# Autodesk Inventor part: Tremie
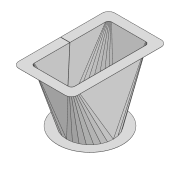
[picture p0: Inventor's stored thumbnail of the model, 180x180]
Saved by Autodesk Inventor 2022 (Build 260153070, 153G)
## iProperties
Created: 2021-07
Part Number: Tremie
Material: Générique
Document SubType Name: Sheet Metal
Designer: Fabian
Density: 1 g/cm^3
Sheet Metal Rule: Par défaut_mm
Appearance: Par défaut
Author: Fabian
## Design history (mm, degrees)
sketch "Esquisse1"
  geometry: L1 (104.999, 0.5)-(74.998, 0.5); L2 (104.999, -0.5)-(74.998, -0.5); L3 (0, 0)-(75, 0); L4 (74.998, 0.5)-(-74.998, 0.5); L5 (74.998, -0.5)-(-74.998, -0.5); A1 r 75 centre (0, 0) between (74.998, 0.5) and (74.998, -0.5); A2 r 105 centre (0, 0) between (104.999, 0.5) and (104.999, -0.5); A3 r 90 centre (0, 0) between (89.999, 0.5) and (89.999, -0.5); 2 further points
  constraints: 10 end point, 10 point on circle, 5 horizontal, 3 centre point, 2 coincident, 2 midpoint, 1 vertical alignment, 1 other
  dimensions: "d0" = 150 diameter of A1; "d1" = 1 distance between parallel lines of L2 L1; "d2" = 30 radial gap between concentric circles of A1 A2; "d3" = 15 radial gap between concentric circles of A2 A3 (= 0.5 x d2)
node "Plan de construction1"
sketch "Esquisse2"
  geometry: L1 (-55, -125)-(55, -125); L2 (55, 125)-(-55, 125); L3 (-65, 115)-(-65, -115); L4 (-65, -125)-(65, 125); L5 (65, -125)-(-65, 125); L6 (75, -155)-(-75, -155); L7 (-95, -135)-(-95, 135); L8 (-75, 155)-(75, 155); L9 (80, -140)-(80, 140); L10 (80, 140)-(-80, 140); L11 (-80, 140)-(-80, -140); L12 (-80, -140)-(80, -140); L13 (74.998, 0.5)-(-74.998, 0.5) reference; L14 (74.998, -0.5)-(-74.998, -0.5) reference; L15 (65, -115)-(65, -0.5); L16 (65, 0.5)-(65, 115); L17 (95, 135)-(95, 0.5); L18 (95, -0.5)-(95, -135); L19 (95, 0.5)-(65, 0.5); L20 (65, -0.5)-(95, -0.5); A1 r 10 centre (55, -115) between (55, -125) and (65, -115); A2 r 10 centre (-55, -115) between (-65, -115) and (-55, -125); A3 r 10 centre (-55, 115) between (-55, 125) and (-65, 115); A4 r 10 centre (55, 115) between (65, 115) and (55, 125); A5 r 20 centre (75, -135) between (75, -155) and (95, -135); A6 r 20 centre (-75, -135) between (-95, -135) and (-75, -155); A7 r 20 centre (-75, 135) between (-75, 155) and (-95, 135); A8 r 20 centre (75, 135) between (95, 135) and (75, 155); 5 further points
  constraints: 36 end point, 20 point on line, 16 point on circle, 16 tangent, 8 centre point, 8 parallel, 6 equal radius, 6 perpendicular, 3 collinear, 2 midpoint, 1 horizontal, 4 other
  dimensions: "d5" = 130 distance of L5.end L4.end; "d6" = 250 distance of L4.end L5.start; "d10" = 30 distance between parallel lines of L6 L1 (= d9); "d18" = 30 distance between parallel lines of L18 L15 (= d10); "d19" = 15 distance between parallel lines of L9 L17 (= 0.5 x d10); "d20" = 15 distance between parallel lines of L2 L10 (= d19); "d56" = 10 radius of A1; "d57" = 20 radius of A5
node "Face lissée1"
node "Face1"
node "Face2"
node "Tremi"
feature "Pli1" dims "d11" = 0.5 (= Epaisseur), "d13" = 0.5 (= RayonPli), "d14" = 0.5 (= LargeurGrugeage), "d15" = 0.25 (= ProfondeurGrugeage), "d16" = 1 (= RestesMinimum), "d17" = 0.5 (= Rayondetransition), "SeamGap" = 0.01
feature "Plaque1" dims "d31" = 0.5 (= Epaisseur)
feature "Plaque2" dims "d32" = 0.5 (= Epaisseur)
node "Bride_rect"
node "Bride_circ"
other parameters: "Epaisseur" = 0.5, "RayonPli" = 0.5 (= Epaisseur), "LargeurGrugeage" = 0.5 (= Epaisseur), "ProfondeurGrugeage" = 0.25 (= 0.5 x Epaisseur), "TailleGrugeage" = 2 (= 4 x Epaisseur), "RestesMinimum" = 1 (= 2 x Epaisseur), "Rayondetransition" = 0.5 (= RayonPli), "TailleRayonJacobi" = 0.5 (= RayonPli), "TailleJeu" = 0.5 (= Epaisseur), "d8" = 15 (= 0.5 x d7), "d9" = 30 (= d2), "d12" = 0.5
